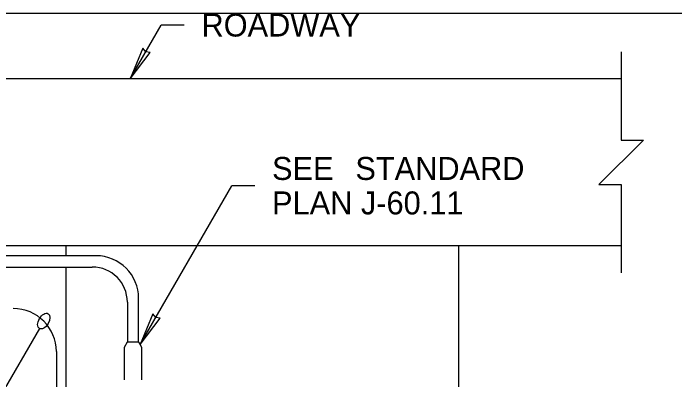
# Model space of a CAD drawing. Extents: x 99862 to 103680, y 99470 to 102076.
# Drawn here: x 101296.6 to 101756.9, y 101820.4 to 102075.8 of the extents above; entities that cross this region are included whole.
import ezdxf

# ---------------------------------------------------------------- set-up
doc = ezdxf.new("R2010")
doc.units = 0
for name, color, linetype in [('Level 1', 7, 'Continuous'), ('Level 10', 7, 'Continuous'), ('Level 15', 7, 'Continuous'), ('Level 20', 7, 'Continuous'), ('Level 9', 7, 'Continuous')]:
    doc.layers.add(name, color=color, linetype=linetype)

msp = doc.modelspace()

# ---------------------------------------------------------------- linework, layer by layer
at = {"layer": 'Level 1'}
msp.add_lwpolyline([(99862, 99999.5), (103151, 99999.5), (103151, 102075.5), (99862, 102075.5)], close=True, dxfattribs=at)
at = {"layer": 'Level 10'}
for p, q in [((101719.61, 102030.05), (101206.1, 102030.05)), ((101719.61, 101913.66), (101206.1, 101913.66)), ((101333.47, 101906.81), (101333.47, 101913.48)), ((101606.65, 101601.99), (101606.65, 101913.48)), ((101333.47, 101802.62), (101333.47, 101898.99))]:
    msp.add_line(p, q, dxfattribs=at)
at = {"layer": 'Level 15'}
for p, q in [((101378.01, 102030.05), (101399.64, 102067.52)), ((101415.64, 102067.52), (101399.64, 102067.52)), ((101384.87, 101845.03), (101448.72, 101955.62)), ((101464.72, 101955.62), (101448.72, 101955.62)), ((101314.86, 101856.08), (101272.89, 101783.38)), ((101326.65, 101840.06), (101326.65, 101795.37))]:
    msp.add_line(p, q, dxfattribs=at)
for points in [[(101378.01, 102030.05), (101392.01, 102048.33), (101388.89, 102048.91), (101386.84, 102051.31)], [(101384.87, 101845.03), (101398.87, 101863.3), (101395.76, 101863.88), (101393.7, 101866.29)]]:
    msp.add_lwpolyline(points, close=True, dxfattribs=at)
msp.add_lwpolyline([(101719.61, 102048.79), (101719.61, 101987.34), (101735.09, 101987.34), (101704.12, 101956.37), (101719.61, 101956.37), (101719.61, 101894.92)], dxfattribs=at)
msp.add_arc((101296.65, 101840.06), 30, 0, 90, dxfattribs=at)
msp.add_ellipse((101317.86, 101861.28), major_axis=(3, 5.2), ratio=0.57735, dxfattribs=at)
at = {"layer": 'Level 9'}
for p, q in [((101354.24, 101906.81), (101287.62, 101906.81)), ((101255.62, 101898.99), (101351.64, 101898.99)), ((101383.89, 101846.98), (101383.89, 101877.16)), ((101376.07, 101874.56), (101376.07, 101846.98)), ((101374.12, 101843.07), (101376.07, 101846.98)), ((101376.07, 101846.98), (101383.89, 101846.98)), ((101383.89, 101846.98), (101385.85, 101843.07)), ((101374.12, 101820.43), (101374.12, 101843.07)), ((101385.85, 101843.07), (101385.85, 101820.43))]:
    msp.add_line(p, q, dxfattribs=at)
for centre, radius, start, end in [((101354.24, 101877.15), 29.66, 0.0041, 90.0041), ((101354.24, 101907.21), 0.4, 270, 270.0041), ((101351.64, 101874.56), 24.43, 0.0041, 90.004), ((101375.69, 101874.56), 0.386, 360, 0.0041)]:
    msp.add_arc(centre, radius, start, end, dxfattribs=at)

# ---------------------------------------------------------------- texts
at = {"layer": 'Level 20'}
msp.add_text('ROADWAY', height=16, rotation=360, dxfattribs=at).set_placement((101427.64, 102059.52))
for s, p in [('SEE ', (101476.72, 101959.62)), ('STANDARD', (101534.7, 101959.62)), ('PLAN J-60.11', (101476.72, 101935.62))]:
    msp.add_text(s, height=16, dxfattribs=at).set_placement(p)

doc.saveas('drawing.dxf')
